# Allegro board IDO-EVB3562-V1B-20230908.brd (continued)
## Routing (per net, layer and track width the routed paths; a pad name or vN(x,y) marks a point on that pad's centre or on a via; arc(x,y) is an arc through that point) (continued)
GND_EARTH: length 94.1
  TOP w0.508: 55.18,78.75 55.18,79.33 ; 31.91,78.52 31.91,79.31 ; 51.31,79.33 51.31,78.87
  TOP w1.016: 54.64,79.28 55.18,78.75 J21.SH1 J22.SH2 51.31,78.87 51.72,79.28 ; 32.8,79.41 31.91,78.52 J23.13 J22.SH1 35.62,78.24 34.45,79.41 ; 15.4,79.28 16.42,78.26 J23.14 15.78,77.88 15.27,78.39 ; J21.SH2 70.87,78.36 71.79,79.28
  L2-VCC w0.508: 35.62,78.24 35.62,79.33
  L2-VCC w1.016: 51.98,79.28 51.31,78.62 J22.SH2 J21.SH1 55.18,78.11 54.01,79.28 ; J23.14 16.42,78.39 15.53,79.28 ; 32.67,79.28 31.91,78.52 J23.13 J22.SH1 35.62,78.24 34.45,79.41 ; 71.41,79.41 70.87,78.87 J21.SH2 71.02,77.88 71.91,78.77
  L3-GND w0.508: 70.87,78.36 70.87,79.33 ; 16.42,79.31 16.42,78.26
  L3-GND w1.016: 52.1,79.41 51.31,78.62 J22.SH2 J21.SH1 55.18,78.36 54.01,79.53 ; 15.4,79.28 16.42,78.26 J23.14 15.78,77.88 15.27,78.39 ; J21.SH2 70.87,78.36 71.79,79.28 ; 34.2,79.28 35.6,77.88 J22.SH1 J23.13 31.91,78.39 32.8,79.28
  BOTTOM w0.508: 31.91,78.52 31.91,79.31 ; 35.47,77.88 34.17,77.88 ; 51.31,78.62 51.31,79.33
  BOTTOM w1.016: 71.15,79.41 70.87,79.13 J21.SH2 ; 16.16,77.88 J23.14 16.42,78.52 15.65,79.28 ; 16.16,77.88 14.76,77.88 14.51,77.63 ; 16.16,77.88 15.02,79.03 ; 34.32,79.03 35.47,77.88 J22.SH1 J23.13 31.91,78.52 32.67,79.28 ; J21.SH2 71.28,77.88 72,78.6 72,78.64 71.83,78.8 71.79,78.8 J21.SH2 ; J22.SH2 51.31,78.62 52.03,79.34 53.72,79.34 J21.SH1 J22.SH2
  vias: v1(15.09,89.22) v1(15.27,86.65) v1(15.27,83.98) v1(15.27,81.19) v1(17.08,89.22) v1(18.07,88.04) v1(18.35,89.22) v1(19.62,89.22) v1(20.89,89.22) v1(20.86,88.04) v1(22.16,89.22) v1(23.43,89.22) v1(23.53,88.04) v1(24.7,89.22) v1(25.97,89.22) v1(27.34,89.22) v1(27.59,88.04) v1(28.61,89.22) v1(29.88,89.22) v1(31.15,89.22) v1(31.66,88.04) v1(32.42,89.22) v1(33.69,89.22) v1(33.69,86.39) v1(33.69,83.6) v1(33.69,80.93) v1(33.69,76.99) v1(34.96,89.22) v1(35.72,88.04) v1(36.23,89.22) v1(37.5,89.22) v1(38.77,89.22) v1(39.66,88.04) v1(40.04,89.22) v1(41.31,89.22) v1(42.78,89.21) v1(43.85,88.04) v1(44.05,89.21) v1(45.32,89.21) v1(46.59,89.21) v1(47.78,88.04) v1(47.86,89.21) v1(49.13,89.21) v1(50.4,89.21) v1(51.67,89.21) v1(51.85,88.04) v1(52.94,89.21) v1(53.12,85.5) v1(53.12,82.71) v1(53.25,79.41) v1(53.25,76.99) v1(54.21,89.21) v1(55.48,89.21) v1(55.91,88.04) v1(56.75,89.21) v1(58.15,89.21) v1(59.42,89.21) v1(59.98,88.04) v1(60.69,89.21) v1(61.96,89.21) v1(63.23,89.21) v1(64.04,88.04) v1(64.5,89.21) v1(65.77,89.21) v1(66.71,88.04) v1(67.04,89.21) v1(68.31,89.21) v1(69.58,89.21) v1(70.85,89.21) v1(70.77,88.04) v1(71.91,85.5) v1(71.91,82.84) v1(71.91,80.17) v1(72.12,89.21)
VCC1V2_DVP: length 66.4
  TOP w0.203: 5.88,19.08 5.81,19.01 J20.22
  TOP w0.254: C1023.2 36.71,7.56 J18.28
  TOP w0.508: C1030.2 7.77,20.1 v1(7.31,19.65) 6.75,19.08 5.88,19.08 ; v1(30.72,7.91) 30.72,3.35 31.66,2.41 36.3,2.41 37.07,3.18 v1(37.07,4.34) ; R136.2 C1048.2 50.64,8.26 v1(50.32,7.95) 55.76,7.95 C104.2 56.22,9.55 C103.2 56.2,9.58 55.56,9.58 55.2,9.22 U13.5 ; C1023.2 v1(38.01,8.16)
  BOTTOM w0.508: v1(50.32,7.95) 50.32,5.64 49.03,4.34 v1(37.07,4.34) ; 19.86,9.3 25.69,9.3 27.08,7.91 v1(30.72,7.91) 32.09,9.28 34.27,9.28 35.52,8.03 37.88,8.03 v1(38.01,8.16)
VCC1V5_DVP: length 19.3
  TOP w0.254: R138.2 C369.2 15.2,10.77 16.67,9.3 16.67,8.97 17.61,8.03 18.88,8.03 19.15,8.31 C108.2
  TOP w0.305: J19.3 23.71,7.37 24.67,8.34 24.67,8.6 C1026.2
  TOP w0.508: v1(25.3,8.43) 25.18,8.55 C1026.2 ; v1(19.84,8.54) 19.72,8.67 C108.2 19.15,9.81 C107.2 19.27,9.94 U14.5
  BOTTOM w0.508: v1(25.3,8.43) 25.19,8.54 v1(19.84,8.54)
VCC1V8_DVP: length 63.3
  TOP w0.203: J20.24 5.52,19.41 6.33,20.22 6.33,20.65 6.8,21.11 7.79,21.11
  TOP w0.254: C101.2 31.34,16.41 31.2,16.27 27.79,16.27 27.27,16.79 R134.2 ; J18.27 37.21,7.36 37.47,7.63 38.22,7.63 38.54,7.95 38.54,8.37 C1027.2
  TOP w0.305: C1024.2 24.16,8.44 23.21,7.48 J19.4 ; v1(9.48,17.1) 9.49,17.1 10.88,17.1 11.15,17.37 R417.2
  TOP w0.508: 32.04,16.03 30.64,14.64 30.64,9.3 30.06,8.72 v1(30.06,7.25) ; C1029.2 7.79,21.11 v1(7.15,20.48) ; v1(22.49,7.72) 22.59,7.72 23.98,9.11 C1024.2 ; C1027.2 v1(39.02,8.21) ; R113.2 v1(42.07,8.18)
  BOTTOM w0.508: 13.52,10.5 16.3,7.72 v1(22.49,7.72) 24.19,7.72 24.65,7.25 v1(30.06,7.25) 32.42,7.25 32.52,7.35 38.16,7.35 v1(39.02,8.21) 39.02,7.91 39.53,7.4 41.29,7.4 v1(42.07,8.18)
VCC2V8_DVP: length 27.5
  TOP w0.203: J20.8 4.85,16.19 5.09,16.19 5.22,16.06 5.85,16.06 6.81,17.03 C1028.2 ; 3.43,19.81 J20.25
  TOP w0.254: C98.2 11.91,9.42 11.54,9.05 10.14,9.05 9.88,9.31 R132.2
  TOP w0.381: v1(5.57,21.22) 4.22,21.22 3.82,20.81 3.82,20.2 3.43,19.81
  TOP w0.508: C1028.2 7.84,16.72 7.22,16.1 v1(6.88,16.1)
  BOTTOM w0.508: v1(11.92,8.62) 8.77,11.76 8.77,14.18 6.88,16.07 v1(6.88,16.1) 6.88,17.45 4.91,19.42 4.91,20.8 5.33,21.22 v1(5.57,21.22)
VCC2V8_DVP1: length 5.7
  TOP w0.254: C1016.2 28.17,9.93 27.9,9.66 26.83,9.66 26.7,9.79 26.7,10.5 26.11,11.09 24.71,11.09 24.09,11.71 R1066.2
VCC2V8_DVP2: length 12.4
  TOP w0.254: J18.24 38.71,7.47 38.89,7.65 39.28,7.65 v1(39.78,8.16) ; C1020.2 35.28,8.59 34.96,8.26 34.04,8.26 33.67,7.89 31.8,7.89 31.59,8.1 C1025.2 R1069.2
  BOTTOM w0.508: v1(39.78,8.16) 39.78,8.54 39.28,9.05 37.85,9.05 37.56,8.76 v1(35.96,8.76)
VCC3V3_E: length 19.1
  TOP w0.381: C1041.2 98.14,27.34 97.57,27.34 97.06,26.83 97.06,22.38 98.71,20.73 102.65,20.73 103.28,21.37 104.63,21.37 106.15,22.89 C1039.2 R1170.2
VCC3V3_PHY0: length 54
  TOP w0.508: v1(45.56,49.73) 45.67,49.84 49.55,49.84 v1(50.18,49.21) ; v1(58.11,64.37) 55.48,64.37 53.63,66.23 R189.2 R175.2 52.61,67.02 51.94,66.35 51.75,66.35 49.53,64.13 v1(49.53,63.94)
  BOTTOM w0.203: U16.40 51.93,59.11 51.72,59.32 51.72,59.7 ; 52.66,54.03 52.99,54.36 U16.29
  BOTTOM w0.381: 51.72,59.7 51.17,60.25 51.17,61.31 50.14,62.34 50.14,62.51 C334.2
  BOTTOM w0.508: v1(50.18,49.21) 50.77,49.8 C360.2 50.9,50.07 51.87,51.04 51.87,52.36 51.68,52.55 C333.2 51.21,53.06 51.86,53.7 52.33,53.7 52.66,54.03 ; C334.2 49.49,63.17 49.49,63.9 v1(49.53,63.94) 47.93,63.94 46.9,62.9 46.9,61.22 46.5,60.82 45.62,60.82 44.27,59.47 44.27,51 45.54,49.73 v1(45.56,49.73) ; v1(58.11,64.37) 58.38,64.37 58.6,64.15 58.6,62.16 58.56,62.11 58.56,60.9 58.92,60.54 C335.2
VCC3V3_PHY2: length 72.2
  TOP w0.508: v1(73.66,73.76) 73.64,73.74 R150.2 73.92,73.06 74.31,72.67 74.31,71.42 73.27,70.38 70.05,70.38 v1(68.18,68.51) ; v1(70.2,61.06) 70.2,57.75 72.17,55.78 v1(72.17,54.77) 72.17,54.47 73.11,53.53 73.11,51.93 73.54,51.49 74.09,51.49 v1(74.75,52.15) ; R157.2 55.4,66.61 56.07,65.94 56.77,65.94 57.66,66.83 57.66,68.68 58.9,69.91 63.78,69.91 65.87,67.82 v1(65.87,66.89)
  BOTTOM w0.203: U15.23 72.69,54.47 C326.2 ; U15.11 76.68,59.05
  BOTTOM w0.254: 71.69,60.25 U15.32
  BOTTOM w0.508: 71.69,60.25 71.48,60.46 70.8,60.46 v1(70.2,61.06) 69.5,61.75 C327.2 69.19,62.09 67.72,63.56 67.72,65.95 66.79,66.89 v1(65.87,66.89) 66.89,67.9 67.57,67.9 v1(68.18,68.51) ; C326.2 v1(72.17,54.77) ; R160.2 78.88,62.59 78.88,66.94 78.74,67.09 78.74,68.62 73.66,73.7 v1(73.66,73.76) ; v1(74.75,52.15) 74.96,52.37 R161.1 R156.1
VCC3V3_SD_OUT: length 28.8
  TOP w0.508: v1(88.42,31.91) 86.65,31.91 84.41,29.67 84.41,28.53 83.07,27.19 M1.9
  TOP w1.016: v1(102.89,32.03) 102.13,32.03 v1(102.09,31.99) 101.97,31.99 101.1,32.86 93.22,32.86 92.79,32.44 91.47,32.44 ; v1(101.87,55.88) 101.87,51.11 v1(103.54,49.44) v1(103.54,48.65)
  vias: v1(90.08,33.94) v1(90.58,33.31) v1(101.19,55.89) v1(109.63,69.76) v1(110.27,69.76)
VCC3V3_SY8368: length 2.4
  TOP w0.254: C814.1 22.41,57.31 23.51,56.21 U70.8
VCC3V3_SYS: length 181.3
  TOP w0.254: v1(68.2,37.55) 68.2,39.63 68.68,40.1 68.68,42.51 67.98,43.21 67.98,48.28 64.57,51.68 64.57,52.84 61.63,55.79 v1(61.63,57.82) ; v1(75.74,73.32) 75.74,70.91 73.82,68.99 70.52,68.99 67.34,65.82 67.34,64.93 66.2,63.79 v1(65.06,63.79) ; v1(23.4,32.16) C31.2 R8.2 ; R431.1 111.3,72.75 111.03,72.47 v1(111.03,70.9) ; v1(92.11,74.58) 94.01,72.68 94.01,71.28 v1(92.87,70.14) ; v1(107.98,64.17) 107.35,63.53 v1(97.31,63.53)
  TOP w0.381: 59.77,25.61 59.77,19.87 60.3,19.34 60.98,19.34 v1(61.46,18.86) ; v1(63.91,16.31) 66.23,14 67.6,14 68.36,13.24 D48.A ; v1(17.79,32.32) 17.79,29.47 17.15,28.83 4.89,28.83 3.46,30.26 2.19,30.26 1.72,30.73 1.72,42 2.5,42.78 v1(5.37,42.78)
  TOP w0.508: R241.1 128.27,24.62 128.5,24.39 R1174.2 ; 122.11,33.08 121.44,32.42 R1211.1
  TOP w0.762: v1(120.07,34.42) v1(120.76,34.42) 122.38,32.8 125.38,32.8 125.59,32.6 129.98,32.6 130.59,31.99 130.59,26.07 129.19,24.67 R241.1
  BOTTOM w0.254: v1(92.11,74.58) 91.85,74.33 81.31,74.33 79.79,72.8 76.26,72.8 v1(75.74,73.32) ; v1(61.63,57.82) 62.16,57.82 65.06,60.71 v1(65.06,63.79) ; v1(111.03,70.9) 111.03,67.22 v1(107.98,64.17) ; v1(97.31,63.53) 96.17,63.53 92.49,67.22 92.49,69.76 v1(92.87,70.14)
  BOTTOM w0.381: v1(61.46,18.86) 63.91,16.41 v1(63.91,16.31) ; R62.1 6.64,44.15 5.37,42.88 v1(5.37,42.78)
  vias: v1(16.67,33.56) v1(28.99,31.15) v1(28.99,30.39) v1(31.27,39.1) v1(32.04,39.1) v1(32.04,38.34) v1(32.04,37.7) v1(43.92,32.88) v1(43.92,32.11) v1(43.92,31.35) v1(44.69,32.88) v1(44.69,32.11) v1(44.69,31.35) v1(61.83,35.9) v1(61.83,35.14) v1(62.59,35.9) v1(62.59,35.14) v1(92.11,35.97) v1(92.11,35.21) v1(92.87,35.97) v1(92.87,35.21) v1(107.7,33.59) v1(109.1,33.64)
VCC5V0_HUB2: length 1.1
  TOP w1.016: 91.47,77.5 91.07,77.1 J42.10
VCC5V0_HUB3: length 2.3
  TOP w0.508: J7.1 132.11,62.2 ; J7.1 132.11,60.64 ; J7.1 131.34,61.42
VCC5V0_HUB4: length 2.3
  TOP w0.508: 132.11,49.21 J8.1 ; J8.1 131.34,49.99 ; J8.1 132.11,50.77
VCC5V_SYS: length 13.9
  TOP w0.127: v1(88.63,24.98) 88.87,25.21 89.57,25.21
  TOP w0.254: 21.75,44.08 21.75,45.88 20.23,47.4 20.23,51.09 19.52,51.79 C815.1 19.52,54.71 19.46,54.77 R787.1
  TOP w0.381: R1168.2 v1(107.68,69.76)
  vias: v1(24.15,37.75) v1(24.16,38.39) v1(24.8,38.39) v1(24.8,37.75) v1(25.43,38.39) v1(25.43,37.75) v1(75.72,32.04) v1(75.72,31.27) v1(76.49,32.04) v1(76.49,31.27) v1(79.1,42.96) v1(79.1,42.27) v1(79.79,42.96) v1(79.79,42.27) v1(80.47,42.96) v1(80.47,42.27) v1(87.28,56.67) v1(87.28,55.91) v1(88.04,56.67) v1(88.04,55.91) v1(88.22,25.38) v1(88.53,25.94) v1(89.11,25.99) v1(89.67,25.99) v1(97.57,71.28) v1(98.33,71.28) v1(99.09,71.79) v1(99.47,22.22) v1(99.47,21.5) v1(100.21,22.22) v1(100.24,21.5) v1(101,22.22) v1(101,21.5) v1(104.43,73.44) v1(105.32,73.31) v1(106.2,73.44) v1(123.73,35.59) v1(123.73,34.96) v1(124.37,35.59) v1(124.37,34.96) v1(125,35.59) v1(125,34.96) v1(126.65,47.4) v1(126.65,46.77) v1(127.03,56.93) v1(127.29,47.4) v1(127.29,46.77) v1(127.67,57.06) v1(127.92,57.56)
VCC_1V8_OUT: length 158.1
  TOP w0.381: R16.1 21.88,12.68 22.18,12.98 22.18,15.56 21.88,15.86 v1(21.88,16.42) ; v1(19.9,28.99) 21.08,30.18 21.08,33.2 19.99,34.3 ; v1(21.14,39.98) 21.14,38.98 21.64,38.48 21.64,35.95 19.99,34.3 ; R1197.2 10.25,34.68 11.51,35.93 14.23,35.93 14.83,35.34 16.61,35.34 17.65,34.3 19.99,34.3 ; v1(37.27,17.13) 37.27,15.44 38.26,14.45 R14.1 R13.1 ; R15.1 22.94,12.09 22.94,15.99 v1(22.89,16.04) ; v1(30.45,28.33) 30.45,27.27 31.15,26.58 31.15,25.94 31.47,25.62 R1078.1 31.78,25.18 31.71,25.11 R382.1
  TOP w0.508: v1(85.88,37.12) 83.95,35.19 M1.17
  TOP w1.016: v1(34.7,40.69) 34.7,41.82 35.16,42.27 v1(35.16,46.28)
  BOTTOM w0.381: v1(19.9,28.99) 23.22,28.99 24.42,27.8 29.66,27.8 30.18,28.33 v1(30.45,28.33) 30.45,28.59 31.94,30.09 34.24,30.09 34.74,29.59 36.39,29.59 37.88,28.1 37.88,26.18 42.8,21.26 42.8,19.65 40.37,17.22 38.07,17.22 37.98,17.13 v1(37.27,17.13) 35.86,17.13 35.77,17.22 27.42,17.22 27.3,17.09 25.98,17.09 25.31,16.42 23.98,16.42 23.54,15.99 22.94,15.99 v1(22.89,16.04) 22.25,16.04 v1(21.88,16.42)
  BOTTOM w1.016: 15.02,61.5 16.29,60.23 16.29,56.17 15.73,55.61 15.73,49.75 16.19,49.29 16.19,44.92 v1(21.14,39.98) 26.42,39.98 27.12,40.69 v1(34.03,40.69) v1(34.7,40.69) ; v1(35.16,46.28) v1(35.97,46.28) 36.85,46.28 37.77,45.36 40.68,45.36 42.73,43.31 44,43.31 v1(45.56,41.75)
  vias: v1(7.74,63.47) v1(8.42,63.46) v1(46.25,41.07) v1(62.11,38.01) v1(62.14,37.32)
VCC_3V3: length 348.9
  TOP w0.254: v1(128.3,12.35) 128.3,10.62 126.86,9.18 124.26,9.18 v1(124.24,9.15)
  TOP w0.381: v1(106.84,6.85) 106.88,6.89 R425.1 ; C1036.2 110.6,16.03 110.19,15.62 U42.16 ; v1(130.21,43.72) 130.33,43.72 131.35,42.7 131.35,40.55 128.3,37.5 v1(128.3,37.12) ; R415.1 v1(76.74,86.52) ; R19.1 v1(77.76,83.85)
  TOP w0.508: v1(124.19,42.74) 124.21,42.72 124.46,42.72 125.49,41.69 R261.2 ; v1(77.04,73.69) 77.43,73.31 77.43,71.69 v1(77.15,71.41) ; R1077.1 v1(124.24,9.15) ; v1(126.4,81.44) 126.4,77.63 125.1,76.33 125.1,73.69 126.65,72.14 v1(126.65,71.91) 126.3,71.56 125.25,71.56 124.52,72.3 R314.2 ; C1036.2 111.09,16.47 111.69,17.08 111.69,17.71 111.18,18.22 109.51,18.22 109.41,18.32 ; v1(131.35,68.74) 117.06,68.74 R466.1
  TOP w0.762: v1(124.19,42.74) v1(124.19,42.07) 124.19,38.87 125.94,37.12 v1(128.3,37.12) v1(128.3,36.35) ; 105.21,7.65 105.21,8.28 107.95,11.02 107.95,16.34 109.41,17.8 v1(109.41,20.46) ; R437.2 105.04,40.52 104.93,40.62 ; v1(106.74,20.46) 106.74,20.68 106.42,21.01 R1201.2 105.39,21.01 104.93,20.56 103.87,20.56 102.78,19.46 101.29,19.46 R299.1 ; 104.93,40.62 v1(104.93,40.67) ; 104.93,40.62 v1(104.93,40.11) ; 104.93,40.62 104.83,40.52 R48.2
  L2-VCC w0.508: J15.5 6.76,36.52 ; J15.5 6.09,35.85 ; J15.5 7.44,35.85
  L2-VCC w0.762: v1(38.58,65.79) 42.76,65.79 43.11,65.44 v1(58.15,65.44) 57.61,65.98 57.61,68.21 59.24,69.83 63.79,69.83 65.92,67.7 68.99,67.7 71.91,70.62 76.75,70.62 77.15,71.02 v1(77.15,71.41)
  BOTTOM w0.254: R460.2 128.87,12.35 v1(128.3,12.35)
  BOTTOM w0.381: v1(126.65,71.91) 129.83,68.74 v1(131.35,68.74) 132.65,68.74 133.27,68.11 133.27,48.62 131.86,47.21 131.86,45.5 130.21,43.85 v1(130.21,43.72)
  BOTTOM w0.508: v1(77.04,73.69) 77.04,83.14 v1(77.76,83.85) 77.76,85.5 v1(76.74,86.52) ; J15.5 7.59,35.85 ; J15.5 6.76,36.67 ; J15.5 6.76,35.02 ; v1(58.15,65.44) 58.43,65.44 v1(58.61,65.26) ; R465.1 v1(126.4,81.44)
  BOTTOM w0.762: 29.37,69.1 29.37,68.23 27.34,66.2 v1(8.69,66.2) ; 29.37,69.1 v1(28.43,69.1) ; 29.37,69.1 29.37,69.3 28.56,69.3 ; v1(27.87,69.07) 28.15,69.07 28.18,69.1 v1(28.43,69.1) ; L12.1 v1(38.58,65.31) v1(38.58,65.79) ; 28.56,69.3 28.23,69.3 v1(27.87,69.65) ; 28.56,69.3 28.43,69.17 v1(28.43,69.1) ; v1(128.3,37.12) v1(128.3,36.35) 128.05,36.1 128.05,24.16 126.78,22.89 123.35,22.89 121.32,20.86 121.32,16.92 123.48,14.76 123.48,11.24 123.35,11.12 123.35,10.32 124.24,9.43 v1(124.24,9.15) 122.8,7.72 118.36,7.72 117.49,6.85 v1(106.84,6.85) v1(104.55,6.85) v1(103.79,6.85) 98.9,6.85 98.07,6.02 86.03,6.02 84.26,4.26 73.49,4.26 ; v1(72.48,4.26) v1(73.07,4.26) 73.49,4.26 ; R194.1 61.75,63.13 60.31,64.57 59.42,64.57 58.66,65.34 58.61,65.34 v1(58.61,65.26) ; 73.49,4.26 73.49,4.58 v1(73.54,4.63) ; v1(77.15,71.41) v1(77.52,71.04) 79.5,69.06 79.5,67.4 79.64,67.26 79.64,63.1 79.99,62.76 R160.1 ; v1(124.19,42.74) v1(124.19,42.07) 123.15,41.03 123.15,40.88 119.58,37.31 107.51,37.31 104.93,39.89 v1(104.93,40.11) v1(104.93,40.67) ; v1(106.74,20.46) v1(109.41,20.46)
  vias: v1(6.38,38.51) v1(7.14,38.51) v1(7.6,64.29) v1(7.91,38.51) v1(8.27,64.29) v1(8.67,65.52) v1(8.67,64.84) v1(13.47,15.68) v1(13.98,16.31) v1(19.9,14.94) v1(20.38,15.93) v1(26.83,26.7) v1(27.59,26.7) v1(28.1,25.94) v1(28.35,26.7) v1(28.48,69.68) v1(28.76,15.02) v1(28.76,14.38) v1(35.54,13.7) v1(36.1,13.27) v1(55.53,12.82) v1(56.29,12.82) v1(73.31,10.7) v1(73.31,10.07) v1(73.95,10.7) v1(73.95,10.07)
VCC_3V3_OUT: length 180
  TOP w0.254: v1(73.82,11.84) 73.69,11.84 72.55,10.7 R11.1 ; R12.1 73.38,13.62 v1(73.69,13.62)
  TOP w0.381: v1(97.57,7.48) 97.8,7.48 99.5,9.18 105.13,9.18 107.26,11.31 107.26,16.63 108.62,18 108.62,23.07 110.21,24.66 R391.2
  TOP w0.508: R383.1 v1(47.59,68.17) ; M1.7 81.32,25.19 81,24.86 81,20.67 79.98,19.65 v1(77.74,19.65) ; v1(83.5,51.59) 84.95,50.14 R384.1 ; v1(65.84,19) 65.84,20.18 64.85,21.17 64.85,22.56 65.88,23.59 65.88,26.14 67.32,27.58 67.32,29.77 66.78,30.31 66.78,40.55 66.35,40.98 66.35,42.18 v1(65.59,42.93) 65.59,46.37 63.89,48.07 63.89,49.31 62.9,50.31 62.9,52.27 56.23,58.94 52.12,58.94 51.74,59.32 49.55,59.32 48.4,60.47 46.65,60.47 46.23,60.9 v1(46.23,61.48) ; v1(77.38,16.67) 77.38,15.65 77.61,15.42 77.61,14.24 76.99,13.62 v1(73.69,13.62)
  BOTTOM w0.254: v1(73.82,11.84) 73.82,13.49 v1(73.69,13.62)
  BOTTOM w0.381: v1(97.57,7.48) 97.57,7.61 96.96,8.21 95.76,8.21 95.57,8.41 94.58,8.41 94.09,7.92 86.72,7.92 81.95,12.68 81.95,14.48 79.76,16.67 v1(77.38,16.67)
  BOTTOM w0.508: v1(83.5,51.59) 81.82,49.92 81.82,47.51 78.82,44.5 67.16,44.5 v1(65.59,42.93) ; v1(65.84,19) 68.61,16.23 71.09,16.23 v1(73.69,13.62) ; v1(46.23,61.48) 45.97,61.73 45.97,66.56 v1(47.59,68.17) ; v1(77.74,19.65) 77.38,19.29 v1(77.38,16.67)
VCC_DCIN: length 35.9
  TOP w0.508: 11.73,75.01 F3.1 13.48,75.01
  TOP w1.524: J1.4 3.11,83.35 3.79,84.03 7.68,84.03 9.02,82.68 9.02,79.61 12.61,76.03 F3.1
  L2-VCC w0.508: 2.7,28.51 J43.5 ; J43.5 1.92,29.29 ; J43.5 3.48,29.29 ; J43.5 2.7,30.07 ; F3.1 13.48,75.01 ; F3.1 11.73,75.01 ; F3.1 12.61,75.89 ; F3.1 12.61,74.14 ; J43.6 3.48,27.29 ; J43.6 2.7,28.07 ; J43.6 1.92,27.29 ; J15.1 7.44,27.85 ; J15.1 6.76,28.52 ; J15.1 6.09,27.85 ; J1.4 4.09,81.4 ; J1.4 3.11,83.08 ; J1.4 2.13,81.4 ; J1.4 3.11,79.72
  vias: v1(10.45,75.47) v1(10.45,74.71) v1(10.55,76.18) v1(11.21,76.23) v1(11.97,76.23) v1(12.73,76.23)
VCC_LEDA+: length 15.4
  BOTTOM w0.508: U10.5 6.26,51.8 6.59,52.13 8.34,52.13 8.97,52.76 8.97,58.22 8.34,58.86 4.47,58.86 4.26,59.06 D18.C
  vias: v1(4.63,58.96) v1(4.86,66.86) v1(4.99,60.99) v1(4.99,60.23) v1(4.96,59.55) v1(5.19,66.35)
VCC_LEDK-: length 10.6
  TOP w0.254: v1(5.49,57.08) 5.57,57.16 5.57,62.77 5.09,63.25 5.09,65.04 v1(5.37,65.31)
  BOTTOM w0.254: R84.2 6.94,56.44 6.13,56.44 v1(5.49,57.08)
  vias: v1(4.81,65.31)
VCC_M2:
  vias: v1(95.55,31.59) v1(95.54,30.91) v1(95.55,30.23) v1(95.55,29.55) v1(95.55,28.88) v1(95.55,28.2) v1(95.65,45.75) v1(96.31,45.61) v1(96.3,44.99) v1(96.54,38.44) v1(96.54,37.76) v1(96.93,45.63) v1(97,44.95) v1(97.31,38.44) v1(97.31,37.76) v1(98.07,38.44) v1(98.07,37.76)
VCC_OUT: length 37.4
  TOP w0.508: J44.1 122.84,5.51 ; J44.1 123.87,4.48 ; J44.1 121.81,4.48 ; J44.1 122.84,3.45
  BOTTOM w0.508: 122.84,3.45 J44.1 ; J44.1 121.81,4.48 ; J44.1 123.87,4.48 ; J56.1 132.17,24.87 133.38,23.65 133.38,11.08 132.49,10.19 128.18,10.19 v1(124.37,6.38) ; J55.1 90.25,3.67 ; J55.1 89.47,2.9 ; J55.1 91.03,2.9 ; J55.1 90.25,2.12
  vias: v1(87.87,4.5) v1(88.63,4.5) v1(89.39,4.5) v1(123.73,5.75) v1(124.37,5.75)
VCC_RMII: length 56.1
  TOP w0.254: v1(35.21,49.27) 34.36,49.27 33.31,50.32 33.31,52.16 R1200.2
  TOP w0.381: R219.1 v1(34.9,70.9)
  TOP w0.508: v1(41.69,57.18) 41.18,57.18 40.77,57.59 40.18,57.59 39.92,57.84 39.92,59.85 40.24,60.17 v1(40.41,60.17) 40.16,60.42 v1(40.16,61.16) ; v1(39.94,64.26) 38.32,64.26 36.36,62.29 36.36,60.75 36.16,60.56 36.16,52.04 v1(35.21,51.09) v1(35.21,49.27)
  BOTTOM w0.254: 37.37,56.42 37.23,56.56 U17.14
  BOTTOM w0.381: v1(34.9,70.9) 35.39,70.9 41.37,64.92 C159.2 ; v1(40.41,60.17) 39.84,59.6 R212.2
  BOTTOM w0.508: v1(35.21,49.27) 33.58,49.27 32.54,50.3 R207.1 R205.1 ; 37.37,56.42 C338.2 38.7,56.09 39.06,55.74 40.88,55.74 41.69,56.55 v1(41.69,57.18) 41.16,57.72 40.52,57.72 39.78,58.45 R195.2 ; R204.2 v1(35.21,51.09)
VCC_SIM: length 14.1
  TOP w0.508: R52.2 R53.2 v1(119.74,53.02) ; 114.33,59.6 114.33,56.57 114.71,56.19 v1(114.71,55.52) R440.2
  BOTTOM w0.508: v1(119.74,53.02) 119.74,52.98 119.14,52.39 118.58,52.39 117.85,53.12 115.98,53.12 114.71,54.39 v1(114.71,55.52)
  vias: v1(109.53,60) v1(110.29,60) v1(116.31,59.06) v1(117.1,59.06)
VCC_SYS: length 7
  TOP w0.305: v1(22.99,53.37) 22.82,53.2 21.77,53.2 21.43,53.54 R783.1
  BOTTOM w0.305: v1(24.42,57.76) 24.42,56.8 22.99,55.38 v1(22.99,53.37)
VCC_TP: length 5.9
  TOP w0.254: R449.2 R422.2 R421.2 10.25,32.56 11.15,33.46 C285.2
  TOP w0.508: R423.2 14.78,34.58 14.02,35.34 12.78,35.34
VCCA_RMII: length 18.2
  TOP w0.508: v1(30.77,57.69) 30.77,54.37 31.51,53.63 32.05,53.63 32.56,54.14 32.56,57.09 35.51,60.04 v1(35.51,61.25)
  BOTTOM w0.254: C336.2 29.69,58.71 30.67,58.71 31.31,58.06 U17.30
  BOTTOM w0.508: v1(30.77,57.69) 30.26,58.2 29.69,58.2 C336.2
VCCIO4_IN: length 6.2
  TOP w0.508: R384.2 C271.2 86.32,48.11 85.25,49.19 M1.31
VCCIO5_IN: length 6.4
  TOP w0.508: R383.2 C270.2 49.56,66.83 49.94,66.46 49.94,65.43 48.87,64.37 M1.76
VCCIO6_IN: length 12.7
  TOP w0.381: 37.57,32.19 35.71,32.19 33.61,30.08 33.61,24.33 33.05,23.78 C269.2 R382.2
VCCIO_PHY0: length 50.3
  TOP w0.381: v1(54.49,50.07) 50.42,50.07 50.08,50.41 44.62,50.41 v1(43.49,49.28)
  TOP w0.508: v1(54.49,50.07) 54.49,50.07 v1(57.13,50.07) 57.25,50.07 v1(58.06,49.26) 58.56,48.75 58.85,48.75 v1(59.31,48.29) 59.77,47.83 59.77,46.06 v1(60.7,45.13)
  BOTTOM w0.203: 53.39,54.08 U16.28
  BOTTOM w0.381: v1(60.7,45.13) 63.85,48.28 63.85,53.94 62.67,55.12 62.67,55.51 60.74,57.44 R191.2 ; v1(43.49,49.28) 43.2,49.56 43.16,49.56 R188.2 ; v1(59.31,48.29) 60.1,49.09 R178.2 ; v1(58.06,49.26) 58.06,49.62 R185.2
  BOTTOM w0.508: R182.2 57.82,50.88 57.13,50.19 v1(57.13,50.07) ; v1(54.49,50.07) C358.2 53.35,50.41 53.35,52.25 53.05,52.55 C361.2 52.61,53.02 53.39,53.8 53.39,54.08
VDD10_PHY0: length 45.9
  TOP w0.508: v1(59.81,54.43) 58.05,56.19 52.69,56.19 51.98,56.9 51.98,57.65 v1(50.96,58.66) ; v1(55.39,60.36) 53.52,60.36 v1(53.39,60.48) 53,60.88 v1(50.18,60.88) ; v1(47.28,51.72) v1(44.99,51.72)
  BOTTOM w0.203: U16.3 v1(53.39,60.48) ; U16.21 56.19,54.72 56.33,54.58 56.87,54.58 ; v1(50.96,58.66) 50.99,58.63 51.28,58.63 51.6,58.31 U16.38 ; U16.8 v1(55.39,60.36)
  BOTTOM w0.508: C328.2 60.75,52.92 60.75,53 59.81,53.94 v1(59.81,54.43) 59.66,54.58 56.87,54.58 ; v1(50.96,58.66) 50.82,58.81 50.82,59.12 50.18,59.75 v1(50.18,60.88) 49.94,61.12 C332.2 49.51,60.68 49.15,60.33 46.9,60.33 46.76,60.18 45.88,60.18 44.9,59.21 44.9,51.81 v1(44.99,51.72) ; v1(55.39,60.36) 55.39,61.05 C331.2 ; C330.2 53.19,60.69 v1(53.39,60.48)
VDD10_RTL: length 32.7
  TOP w0.508: v1(73.82,52.16) 73.82,53.8 73.12,54.51 73.12,55.72 70.86,57.99 v1(70.86,59.34) 70.86,60.44 71.65,61.24 v1(73.09,61.24) 73.1,61.25 v1(75.09,61.25)
  BOTTOM w0.203: U15.3 v1(73.09,61.24) ; U15.8 75.09,60.49 75.85,61.25 75.85,61.71 76.23,62.09 76.23,62.83 C322.2 ; C324.2 69.76,59.15 70.13,59.15 70.52,58.76 71.06,58.76 71.35,59.05 U15.30 ; 73.18,55.54 73.09,55.62 U15.22
  BOTTOM w0.381: v1(75.09,61.25) 75.09,61.61 75.81,62.32 75.81,62.66 C322.2 ; C324.2 70.34,59.72 70.72,59.34 v1(70.86,59.34)
  BOTTOM w0.508: v1(73.09,61.24) 72.17,62.16 72.16,62.16 71.53,62.79 C323.2 ; v1(73.82,52.16) 73.58,51.92 R159.2 73.12,51.98 C126.1 C321.2 73.18,54.07 73.18,55.54
VDD_3V8: length 11.6
  TOP w0.254: v1(94.03,50.54) 94.03,51.42 C80.2 ; R60.2 C79.2 90.46,49.1 v1(90.99,48.57)
  TOP w0.508: R452.2 93.89,59.34 94.01,59.47 95.92,59.47 96.55,58.83
  BOTTOM w0.254: v1(90.99,48.57) 91.78,49.36 92.86,49.36 v1(94.03,50.54)
  vias: v1(96.86,57.26) v1(96.86,56.47) v1(96.86,55.63) v1(97.59,55.66) v1(98.33,55.63) v1(99.09,55.63) v1(102.01,67.72) v1(102.01,67.09) v1(102.83,67.7) v1(102.78,67.09) v1(103.66,67.7) v1(104.53,67.7) v1(105.72,55.79) v1(106.33,55.79) v1(106.97,55.76) v1(107.6,55.76) v1(108.24,55.79) v1(108.77,56.12) v1(120.84,53.04) v1(121.44,53.04)
VDD_5V: length 49.3
  TOP w0.305: v1(83.98,7.14) 84.58,7.14 v1(85.31,6.41)
  TOP w0.508: U43.3 125.64,12.35 125.58,12.41 C532.1 124.06,12.41 123.12,11.46 v1(122.59,11.46) ; R366.1 121.7,8.92 v1(121.19,9.43)
  BOTTOM w0.254: v1(121.19,9.43) 121.19,10.07 v1(122.59,11.46)
  BOTTOM w0.305: v1(121.19,9.43) 120.28,8.52 117.84,8.52 116.94,7.61 98.62,7.61 97.69,6.68 85.58,6.68 v1(85.31,6.41)
  BOTTOM w0.508: 6.76,31.02 J15.3 ; J15.3 6.76,32.67 ; J15.3 5.94,31.85
  vias: v1(14.76,50.83) v1(14.76,50.2) v1(14.76,49.52) v1(15.04,49.03) v1(79.79,14.38) v1(79.79,13.75) v1(80.42,14.38) v1(80.42,13.75)
VDD_LCD: length 5.8
  TOP w0.508: 6.76,33.02 J15.4 ; J15.4 5.94,33.85 ; J15.4 6.76,34.67 ; J15.4 7.59,33.85 ; J15.2 7.59,29.85 ; J15.2 5.94,29.85 ; J15.2 6.76,30.67
VDD_LCD_: length 6.5
  TOP w1.016: J16.1 13.62,45.18 ; J16.1 J16.2 11.62,45.18 ; J16.1 J16.3 ; J16.1 14.45,46.01
VDD_RTC: length 4.2
  TOP w0.381: D49.C D48.C 67.78,12.66 C190.1 67.34,11.72 67.3,11.68 U20.8
4G_DM: length 2.9
  TOP w0.114: J10.36 103.98,56.36 103.73,56.11 103.73,55.16 R49.2
4G_DP: length 3
  TOP w0.114: R50.2 103.48,55.17 103.48,56.09 103.18,56.4 J10.38
4G_LED_WANN#: length 10.7
  TOP w0.127: J10.42 101.58,58.58 100.31,59.85 96.55,59.85 95.79,60.61 LED2.C
4G_POWER_H: length 82.9
  TOP w0.127: v1(44.59,44.14) 44.38,43.93 41.42,43.93 37.68,40.19 37.57,40.19 ; v1(89.91,39.26) 90.22,39.57 90.22,40.22 94,43.99 94,47.12 95.73,48.85 97.21,48.85 98.91,50.55 98.91,50.94 98.55,51.3 95.03,51.3 94.6,50.87 94.6,50.44 93.39,49.24 R441.1
  BOTTOM w0.127: v1(44.59,44.14) 49.49,39.25 61.6,39.25 64.82,42.47 65.78,42.47 66.27,42.96 75.85,42.96 77.78,41.03 84,41.03 86.51,38.51 89.16,38.51 v1(89.91,39.26)
ADC0: length 6.2
  TOP w0.127: R350.2 111.92,5.39 111.64,5.11 111.64,2.98 J44.10
ADC1: length 6.3
  TOP w0.127: J44.12 111.28,3.08 111.28,5.14 110.9,5.52 R349.2
ADC2: length 10.9
  TOP w0.127: R348.2 101.28,5.4 101.28,3.63 101.61,3.3 106.24,3.3 J44.14
ADC3: length 8.4
  TOP w0.127: R347.2 101.02,6.16 101.02,3.53 101.51,3.04 103.96,3.04 J44.16
ADC4: length 9
  TOP w0.127: J44.18 101.45,1.94 100.32,3.07 99.21,3.07 98.69,3.59 98.69,5.42 99.39,6.13 99.97,6.13 R346.2
ADC5: length 6.1
  TOP w0.127: J44.20 98.43,3.49 98.43,5.6 R345.2
AF-PWDN: length 9.1
  TOP w0.127: J20.26 5.51,19.81 6.04,20.34 6.04,20.77 6.85,21.58 9.68,21.58 10.15,21.11 10.15,20.37 R416.2
BATDIV: length 4
  TOP w0.254: M1.176 78.56,34.62 79.11,35.17 v1(79.11,35.51)
  BOTTOM w0.254: TP3.1 79.96,35.51 v1(79.11,35.51)
BT_REG_ON_H: length 1
  TOP w0.127: R235.2 R245.1
BT_REG_ON_H_GPIO0_B0_D: length 65
  TOP w0.127: R235.1 113,16.17 v1(112.79,16.17) ; v1(70.24,28.32) 70.51,28.05 70.51,26.56 70.01,26.07 70.01,24.95 70.14,24.82 70.14,24.56 69.67,24.1 69.67,23.34 69.25,22.92 69.25,21.14 70.06,20.33 71.18,20.33 72.73,18.78 75.32,18.78 75.87,18.23 M1.167
  BOTTOM w0.127: v1(112.79,16.17) 112.6,16.35 110.34,16.35 110.16,16.53 103.47,16.53 102.65,17.35 91.91,17.35 87.2,22.06 86.78,22.06 84.48,24.37 83.72,24.37 79.17,28.91 71.55,28.91 70.95,28.32 v1(70.24,28.32)
CAM_CLK0_OUT_M1: length 5.1
  TOP w0.127: R123.1 33.26,40.49 34.57,39.18 36.11,39.18 36.11,39.19 37.57,39.19
CAM_CLK2_OUT: length 112.7
  TOP w0.127: v1(62.45,21.11) 62.45,22.37 64.17,24.09 64.17,24.54 64.63,25 64.63,26.68 66.05,28.1 66.05,29.22 65.54,29.73 65.54,39.91 65.03,40.42 65.03,41.36 64.24,42.15 64.24,45.8 62.57,47.48 62.57,48.93 61.59,49.91 61.59,50.33 61.59,50.54 61.59,51.15 59.82,52.92 59.4,52.92 57.44,54.88 49.47,54.88 48.77,55.58 46.87,55.58 40.87,61.58 M1.84 ; v1(21.59,15.31) 21.59,13.33 21.37,13.11 21.37,9.62 R1179.1
  BOTTOM w0.127: v1(21.59,15.31) 21.73,15.17 24.39,15.17 24.95,15.73 25.53,15.73 26.26,16.45 34.11,16.45 35.13,15.43 37.31,15.43 38.03,14.71 39.76,14.71 40.3,15.26 41.15,15.26 43.02,17.12 52.84,17.12 53.67,16.3 56.73,16.3 59.89,19.46 60.76,19.46 60.88,19.58 62,19.58 62.09,19.67 62.59,19.67 62.98,20.05 62.98,20.59 v1(62.45,21.11)
CAM_CLK3_OUT: length 89.2
  TOP w0.127: R1180.1 42.32,12.23 40.53,14.02 v1(40.53,14.79) ; v1(62.19,19.16) 62.19,19.3 62.98,20.08 62.98,22.39 64.47,23.88 64.47,24.42 64.9,24.85 64.9,26.55 66.33,27.97 66.33,29.34 65.79,29.88 65.79,40.06 65.34,40.52 65.34,41.56 64.55,42.35 64.55,45.91 62.85,47.61 62.85,49.01 61.84,50.02 61.84,50.23 61.84,50.44 61.84,51.39 60.01,53.21 59.53,53.21 57.58,55.16 49.63,55.16 48.9,55.89 47,55.89 41.87,61.01 M1.83
  BOTTOM w0.127: v1(62.19,19.16) 62.02,19.33 61.06,19.33 60.89,19.16 60.05,19.16 56.9,16.02 53.47,16.02 52.64,16.85 43.15,16.85 41.1,14.79 v1(40.53,14.79)
CAN0_H: length 25.8
  BOTTOM w0.203: L45.2 129.7,16.42 128.56,17.56 126.4,17.56 125.99,17.15 D194.A 124.77,16.8 123.98,16.8 122.97,17.81 122.97,20.23 124.24,21.5 127.67,21.5 130.59,24.42 130.59,27.17 J56.2
CAN0_L: length 28.1
  BOTTOM w0.203: J56.3 130.08,28.66 130.08,24.54 127.41,21.88 123.86,21.88 122.46,20.48 122.46,17.56 123.73,16.29 124.77,16.29 D195.A 125.92,15.93 127.03,17.05 128.18,17.05 128.81,16.42 L46.2
CAN0_RX_M2: length 14.9
  TOP w0.127: U43.4 127.29,11.08 127.41,10.95 127.41,10.68 126.55,9.81 124.62,9.81 124.24,10.19 120.56,10.19 117.89,12.86 R1208.2
CAN0_STB_IO: length 1.8
  TOP w0.127: U43.8 132.24,14.89 v1(132.62,14.51)
  BOTTOM w0.127: v1(132.62,14.51) 132.55,14.44 R459.1
CAN0_TX_M2: length 19.3
  TOP w0.127: R1207.2 115.6,11.97 115.98,12.35 118.02,12.35 120.43,9.94 124.13,9.94 124.51,9.56 126.68,9.56 127.67,10.55 127.67,14.43 127.21,14.89 U43.1
CAN0H: length 4.1
  TOP w0.203: U43.7 129.83,13.62 v1(129.57,13.88)
  BOTTOM w0.203: R462.1 129.99,14.17 L45.1 129.57,14.33 v1(129.57,13.88)
CAN0L: length 5.3
  TOP w0.203: U43.6 131.22,12.35 130.33,13.24 129.45,13.24 v1(128.81,13.88)
  BOTTOM w0.203: R461.1 128.52,14.17 L46.1 v1(128.81,13.88)
CIF1_SCL: length 2.5
  TOP w0.127: J18.21 40.21,7.4 41.05,8.24 R126.2
CIF1_SDA: length 2.6
  TOP w0.127: R127.2 40.42,8.47 40.42,8.01 39.71,7.3 J18.22
CIF2_RST: length 9.7
  TOP w0.127: R372.2 10.28,18.19 10.25,18.17 R417.1 9.57,18.36 8.34,18.36 C288.2 6.89,17.86 5.75,16.73 v1(5.44,16.73) ; v1(4.22,16.33) 3.73,16.33 3.21,15.81 J20.5
  BOTTOM w0.127: v1(4.22,16.33) 4.88,16.33 5.27,16.73 v1(5.44,16.73)
CIF2_RST_L: length 71.6
  TOP w0.127: R372.1 13.23,20.65 v1(17.15,20.65) ; v1(21.89,39.07) 22.02,38.94 22.02,29.1 22.99,28.13 22.99,23.15 24.26,21.87 v1(24.26,18.76) ; v1(35.62,39.78) 35.9,40.06 35.9,45.47 36.61,46.18 36.61,59.6 37.2,60.19 37.57,60.19
  BOTTOM w0.127: v1(17.15,20.65) 19.04,18.76 v1(24.26,18.76) ; v1(21.89,39.07) 26.49,39.07 27.41,39.99 35.41,39.99 v1(35.62,39.78)
CIF2_SCL: length 33.3
  TOP w0.127: v1(4.23,18.82) 4.04,19.01 J20.21 ; v1(13.83,5.04) 15.23,3.63 20.42,3.63 21.71,4.91 J19.7 21.71,7.92 R128.2
  BOTTOM w0.127: v1(4.23,18.82) 4.23,18.6 4.44,18.39 4.44,17.73 4.98,17.19 5.64,17.19 5.91,16.92 5.91,15.7 7.82,13.79 7.82,11.34 13.83,5.34 v1(13.83,5.04)
CIF2_SDA: length 32.8
  TOP w0.127: v1(14.94,5.09) 16.14,3.89 20.32,3.89 21.36,4.93 21.36,5.86 21.21,6.01 J19.8 21.21,8.44 R129.2 ; v1(4.22,19.49) 4.14,19.41 J20.23
  BOTTOM w0.127: v1(4.22,19.49) 4.7,19.01 4.7,17.84 5.09,17.45 5.74,17.45 6.16,17.03 6.16,15.8 8.08,13.89 8.08,11.44 14.43,5.09 v1(14.94,5.09)
CIF_EN: length 69.2
  TOP w0.127: v1(53.94,16.79) 53.7,16.54 R374.1 ; R373.1 26.94,21.19 26.14,21.19 25.86,20.91 25.86,20.3 25.45,19.88 25.45,17 v1(24.28,15.83) 24.09,15.65 R1065.1 ; R375.1 R1181.1 19.1,15.74 19.22,15.74 19.95,16.47 20.61,16.47 v1(20.99,16.85) 20.99,17.23 20.26,17.95 14.72,17.95 11.53,14.77 R130.1 ; v1(34.68,16.62) 33.2,15.15 32.86,15.15 R1172.2 R1068.1
  BOTTOM w0.127: v1(53.94,16.79) 53.3,17.43 42.92,17.43 41,15.51 40.15,15.51 39.72,15.08 38.11,15.08 37.47,15.71 35.59,15.71 v1(34.68,16.62) 34.53,16.77 27.52,16.77 27.46,16.71 26.14,16.71 25.47,16.04 24.49,16.04 v1(24.28,15.83) 23.97,15.53 22.11,15.53 21.41,16.22 21.41,16.42 v1(20.99,16.85)
CIF_PDN: length 59.8
  TOP w0.127: R124.2 43.09,8.48 42.12,7.51 41.4,7.51 41.21,7.33 J18.19 41.21,4.27 38.64,1.71 25.04,1.71 22.21,4.54 ; 22.21,4.54 22,4.34 21.49,4.34 20.53,3.38 14.75,3.38 12.6,5.52 v1(12.6,7.57) ; 22.21,4.54 J19.6 ; R416.1 7.53,19.08 7.06,18.61 6.61,18.61 5.97,17.97 v1(5.44,17.97) 5.29,18.12 5.29,18.4 5.08,18.61 J20.20
  BOTTOM w0.127: v1(5.44,17.97) 5.58,17.97 6.42,17.13 6.42,15.91 8.33,14 8.33,11.55 12.31,7.57 v1(12.6,7.57)
CIF_PDN_L: length 95.1
  TOP w0.127: R124.1 42.44,10.4 42.04,10.4 41.82,10.62 41.82,12.38 40.04,14.15 40.04,15.6 v1(39.27,16.37) ; 37.57,59.19 37.69,59.19 38.72,58.16 38.72,56.87 41.11,54.47 48.29,54.47 48.92,53.84 57.02,53.84 59.82,51.03 59.82,50.24 61.53,48.53 61.53,46.98 63.17,45.34 63.17,41.68 63.97,40.87 63.97,39.95 64.5,39.43 64.5,27.31 64.09,26.91 64.09,25.33 63.61,24.85 63.61,24.34 61.29,22.02 61.29,20.95 61.7,20.54 62.25,20.54 v1(62.51,20.28)
  BOTTOM w0.127: v1(39.27,16.37) 39.48,16.58 40.63,16.58 42.62,18.57 57.06,18.57 59.46,20.97 61.25,20.97 61.68,20.55 62.24,20.55 v1(62.51,20.28)
CIF_PWREN_H: length 104.5
  TOP w0.127: v1(35.37,16.62) 33.41,14.66 33.27,14.66 R1172.1 ; R1082.2 R78.2 40.8,64.32 40.14,63.66 38.36,63.66 36.89,62.19 36.89,61.5 37.2,61.19 38.07,61.19 38.51,60.74 38.51,58.72 38.97,58.27 38.97,56.97 41.21,54.73 48.39,54.73 49.03,54.09 57.12,54.09 60.08,51.14 60.08,50.34 61.78,48.64 61.78,47.09 63.42,45.44 63.42,41.78 64.23,40.98 64.23,40.06 64.75,39.53 64.75,27.19 64.35,26.78 64.35,25.2 63.86,24.72 63.86,24.21 61.77,22.13 v1(61.77,21.12)
  BOTTOM w0.127: v1(35.37,16.62) 35.42,16.67 38.12,16.67 38.29,16.84 40.53,16.84 42.52,18.82 56.96,18.82 59.38,21.24 61.65,21.24 v1(61.77,21.12)
CIF_RST: length 31
  TOP w0.127: R125.2 C94.2 41.31,10.52 R113.1 41.56,9.25 41.56,8.11 40.71,7.26 J18.20 40.71,4.13 38.54,1.96 25.14,1.96 22.71,4.4 J19.5
CIF_RST_L: length 90.5
  TOP w0.127: R125.1 40.04,12.17 40.04,13.79 39.76,14.07 39.76,14.96 v1(38.67,16.05) ; v1(61.84,20.07) 61.63,20.28 61.59,20.28 61.03,20.83 61.03,22.14 63.36,24.47 63.36,25.03 63.84,25.51 63.84,27.03 64.24,27.44 64.24,39.2 63.72,39.72 63.72,40.74 62.92,41.54 62.92,45.23 61.27,46.88 61.27,48.43 59.57,50.13 59.57,50.93 56.96,53.54 44.48,53.54 44.44,53.58 41.64,53.58 38.46,56.76 38.46,58.06 38.33,58.19 37.57,58.19
  BOTTOM w0.127: v1(38.67,16.05) 38.81,15.9 39.46,15.9 39.89,16.33 40.74,16.33 42.73,18.32 57.17,18.32 59.57,20.71 61.15,20.71 61.59,20.28 61.63,20.28 v1(61.84,20.07)
CKXTALIN: length 5
  BOTTOM w0.127: XT4.3 28.54,60.6 C156.1 29.05,59.47 31,59.47 31.41,59.06 U17.32
CKXTALOUT: length 8.4
  BOTTOM w0.127: U17.31 31.4,58.56 30.88,59.09 28.3,59.09 C158.2 27.72,60.29 27.72,62.09 XT4.1
CLKREQB: length 5.2
  BOTTOM w0.102: 76.72,58.65 U15.12
  BOTTOM w0.127: 76.72,58.65 77.34,58.65 77.43,58.56 80.18,58.56 80.25,58.64 R155.2
CSI0_MCLK: length 48.8
  TOP w0.127: J20.14 6.08,17.41 7.03,18.36 7.44,18.36 7.69,18.62 9.35,18.62 11.85,21.12 17.89,21.12 19.49,22.72 19.49,27.03 v1(20.86,28.4) ; v1(32.16,28.55) 32,28.71 32,29.64 32.32,29.96 32.32,30.13 34.7,32.51 34.7,37.5 33.75,38.46 C95.2 33.05,38.46 R123.2
  BOTTOM w0.127: v1(20.86,28.4) 21.07,28.61 23.07,28.61 24.26,27.42 30.45,27.42 31.58,28.55 v1(32.16,28.55)
CSI2_MCLK: length 4.8
  TOP w0.127: R1177.1 R1179.2 20.39,9.54 20.39,8.63 20.71,8.32 J19.9
CSI3_MCLK: length 6.1
  TOP w0.127: R1180.2 R1178.1 43.21,10.45 43.62,10.04 43.62,8.51 43.33,8.21 43.18,8.21 42.21,7.24 J18.17
GMAC0_TXCLK_: length 35.7
  TOP w0.127: v1(58.21,47.32) 57.34,47.32 55.99,48.67 50.84,48.67 50.53,48.36 43.2,48.36 41.85,49.71 v1(41.85,51.72)
  BOTTOM w0.127: v1(41.85,51.72) 41.87,51.7 C132.2 R177.2 ; U16.20 57.56,55.51 57.92,55.15 59.97,55.15 60.51,54.61 60.51,54.23 61.64,53.09 61.64,49.25 59.72,47.32 v1(58.21,47.32)
GMAC1_RSTN: length 4.6
  BOTTOM w0.203: R172.2 R190.1 C364.2 59.02,58.71 U16.12
GMAC1_RSTN_GPIO0_A6_D: length 54.2
  TOP w0.127: v1(61.95,59.41) 62.17,59.41 63.49,58.09 63.49,55.9 66.24,53.15 66.24,52.1 70.43,47.91 70.43,38.94 69.73,38.23 69.73,34.37 69.19,33.83 69.19,32.34 71.01,30.51 71.01,26.31 70.52,25.81 70.52,25.31 70.9,24.93 70.9,24.61 70.18,23.89 70.18,23.13 69.76,22.71 69.76,21.37 70.29,20.84 71.43,20.84 72.98,19.28 75.53,19.28 75.78,19.03 76.49,19.03 76.59,18.93 76.94,18.93 77.22,18.65 77.4,18.65 77.87,18.18 M1.169
  BOTTOM w0.127: R172.1 v1(61.95,59.41)
GPIO0_A5_D: length 58
  TOP w0.127: v1(88.27,59.49) 90.49,59.49 R429.2 R430.2 ; v1(80.37,49.13) 80.96,48.55 80.96,33.36 80.73,33.13 80.73,26.93 79.66,25.86 79.66,24.21 79.28,23.83 76.72,23.83 74.81,21.93 74.81,20.48 75.98,19.31 76.64,19.31 76.77,19.18 77.14,19.18 77.42,18.91 78.41,18.91 78.87,18.45 M1.170
  BOTTOM w0.127: v1(80.37,49.13) 80.58,49.33 80.58,49.61 80.78,49.82 80.78,49.97 83.5,52.69 83.9,52.69 85.08,53.87 85.08,57.98 86.6,59.49 v1(88.27,59.49)
HOST_WAKE_BT_H: length 4.5
  TOP w0.127: R1174.1 127.07,22.87 126.1,22.87 R237.2 U18.6
HOST_WAKE_BT_H_GPIO0_A7_D: length 151.8
  TOP w0.127: R1173.2 74.2,81.57 74.13,81.5 74.13,74.33 v1(74.21,74.25) ; v1(124.65,25.14) 125.83,23.96 125.91,23.96 R237.1 ; v1(83.27,60.82) 83.27,63.2 82.2,64.27 82.2,67.44 80.52,69.13 v1(80.28,69.13) ; v1(79.89,57.47) 78.43,56.02 78.43,50.73 75.77,48.06 75.77,44.21 76.29,43.69 76.29,43.27 75.72,42.7 v1(75.72,41.94) ; M1.168 76.87,18.11 76.21,18.78 75.68,18.78 75.43,19.03 72.86,19.03 71.31,20.58 70.16,20.58 69.5,21.24 69.5,22.81 69.93,23.24 69.93,23.99 70.52,24.58 70.52,24.92 70.26,25.18 70.26,25.94 70.76,26.44 70.76,29.76 v1(70.52,30) 70.52,30.65 68.93,32.23 68.93,33.94 69.47,34.47 69.47,38.38 69.97,38.88 v1(69.97,42.2)
  BOTTOM w0.127: v1(79.89,57.47) 79.98,57.56 81.59,57.56 82.88,58.85 82.88,60.43 v1(83.27,60.82) ; v1(74.21,74.25) 74.21,73.81 76.03,71.99 77.54,71.99 80.28,69.25 v1(80.28,69.13) ; v1(70.52,30) 71.03,30.51 79.02,30.51 84.1,25.43 84.88,25.43 86.98,23.33 87.72,23.33 92.43,18.62 102.81,18.62 103.18,18.25 110.18,18.25 110.34,18.4 116.07,18.4 122.8,25.14 v1(124.65,25.14) ; v1(69.97,42.2) 75.47,42.2 v1(75.72,41.94)
HP_DET_L_GPIO0_B3_D: length 178.4
  TOP w0.127: v1(74.71,11.21) 74.71,4.99 73.44,3.72 68.94,3.72 68.28,3.06 v1(68.28,2.01) ; v1(64.91,19.53) 64.89,19.55 62.93,19.55 62.66,19.28 62.66,18.94 62.29,18.57 62.21,18.57 61.87,18.23 M1.153 ; v1(130.08,34.96) 130.08,38.51 131.86,40.29 131.86,42.83 130.46,44.23 130.46,46.51 130.59,46.64 133.26,46.64 v1(133.51,46.9) ; v1(132.44,70.49) 132.16,70.77 124.56,70.77 R455.1
  BOTTOM w0.127: v1(130.08,34.96) 128.81,33.69 128.81,24.04 127.03,22.26 123.6,22.26 122.08,20.73 122.08,17.18 124.24,15.02 124.24,12.48 125.74,10.98 125.74,8.8 122.73,5.79 122.52,5.79 120.28,5.79 120.07,6 118.76,6 118.27,5.52 99.55,5.52 98.18,4.15 96.35,4.15 95.5,4.99 87.19,4.99 86.75,4.56 86.75,2.2 86,1.45 77.13,1.45 76.9,1.22 69.08,1.22 v1(68.28,2.01) ; v1(74.71,11.21) 74.33,11.59 74.33,13.88 71.53,16.67 68.84,16.67 65.98,19.53 v1(64.91,19.53) ; v1(133.51,46.9) 133.51,47.78 133.76,48.04 133.76,69.17 v1(132.44,70.49)
HP_SNS: length 131.9
  TOP w0.254: J37.4 119.51,82.39 119.51,76.44 118.84,75.76 R316.2 118.84,71.88 120.84,69.88 131.77,69.88 133.35,68.3 133.35,48.13 132.75,47.53 130.33,47.53 129.73,46.92 129.73,45.65 128.43,44.36 v1(127.29,44.36) ; R306.1 91.45,25 v1(91.45,29.76) 91.45,30.66 88.81,33.31 86.37,33.31 83.29,30.23 83.29,29.65 82.83,29.19 M1.11
  BOTTOM w0.254: v1(127.29,44.36) 126.52,44.36 125.51,43.34 125.51,41.95 124.28,40.72 124.28,40.39 120.18,36.29 107.89,36.29 106.08,34.48 106.08,33.02 103.18,30.13 103.18,26.14 102.58,25.53 95.71,25.53 95.05,26.19 94.4,26.19 91.45,29.14 v1(91.45,29.76)
HPL_OUT: length 114.5
  TOP w0.254: C222.2 121.72,70.31 131.88,70.31 133.73,68.46 133.73,47.88 132.87,47.02 130.46,47.02 130.11,46.67 130.11,45.39 128.44,43.72 v1(126.78,43.72) ; C215.1 90.86,24.19 v1(90.86,30.5) 90.86,30.61 88.68,32.8 86.57,32.8 83.75,29.98 83.75,29.18 82.76,28.19 M1.10
  BOTTOM w0.254: v1(90.86,30.5) 90.86,29.19 94.24,25.81 94.89,25.81 95.55,25.15 102.74,25.15 103.56,25.98 103.56,29.97 106.46,32.86 106.46,34.32 107.22,35.08 112.25,35.08 113.07,35.91 120.34,35.91 124.66,40.23 124.66,40.56 126.02,41.92 126.02,42.96 v1(126.78,43.72)
HPL_OUT+: length 10.7
  TOP w0.254: J37.2 124.06,80.78 122.64,79.36 122.64,78.11 120.96,76.44 D66.1 120.96,73.92 120.99,73.89 R447.2 120.99,73 121.44,72.55 C222.1
HPR_OUT: length 113.7
  TOP w0.254: M1.12 82.59,30.19 86.22,33.81 88.86,33.81 v1(91.98,30.69) 91.98,30.16 91.98,30.16 91.98,25.56 92.24,25.31 C219.1 ; v1(127.79,44.99) 128.43,44.99 129.34,45.91 129.34,47.18 130.21,48.04 132.62,48.04 132.97,48.38 132.97,68.14 131.66,69.45 120.63,69.45 118.49,71.6 C224.2
  BOTTOM w0.254: v1(127.79,44.99) 126.4,44.99 125,43.59 125,41.98 123.89,40.88 123.89,40.55 120.02,36.67 107.73,36.67 105.7,34.64 105.7,33.18 102.8,30.29 102.8,26.3 102.42,25.91 95.86,25.91 95.21,26.57 94.56,26.57 91.98,29.15 91.98,30.64 91.98,30.64 v1(91.98,30.69)
HPR_OUT+: length 13.4
  TOP w0.254: J37.3 117.44,83.49 118.96,81.97 118.96,78.09 116.65,75.78 D68.1 117.13,73.97 C224.1
HUB_1V8: length 14.5
  TOP w0.254: C303.2 118.42,44.86 118.19,45.1 U7.9 ; C310.2 106.97,45.12 107.49,44.6 U7.29 ; C355.2 118.78,41.56 118.24,42.1 U7.3 ; C305.2 107.47,47.6 107.47,46.52 107.89,46.1 U7.26
  TOP w0.508: v1(118.65,45.55) 119.34,44.86 ; v1(119.13,40.77) 119.47,41.12 C355.2 ; C310.2 106.53,44.72 v1(106.79,44.46) ; v1(107.53,48.55) C305.2
HUB_3V3: length 21.8
  TOP w0.254: U7.32 107.72,43.1 107.17,42.55 C306.2 ; C309.1 112.69,50 U7.19 ; C308.1 107.09,46.58 107.09,46.26 107.76,45.6 U7.27
  TOP w0.508: v1(120.94,43.21) 120.63,43.21 R435.1 R436.1 ; R45.2 R48.1 103.34,39.9 104.33,38.91 105.63,38.91 ; R434.1 v1(120.42,39.28) ; C309.1 112.99,50 v1(113.37,50.38) ; C308.1 v1(106.53,47.78) ; v1(116.62,38.79) 116.62,37.02 116.27,36.67 R439.2 ; v1(107.73,38.62) 105.93,38.62 105.63,38.91 ; v1(106.53,43.14) C306.2 ; 105.63,38.91 R438.2
  vias: v1(111.08,38.34) v1(111.95,38.26) v1(116.01,49.23) v1(116.7,49.21)
HUB_DM1: length 11.3
  TOP w0.114: R49.1 103.72,53.62 103.72,51.92 105.91,49.73 110.1,49.73 110.56,49.28 110.56,49.02 110.69,48.89 U7.23
HUB_DM2: length 40.8
  TOP w0.114: R37.1 87.34,70.07 87.21,69.94 87.21,69.67 v1(87.49,69.39) ; v1(106.63,51.45) 106.91,51.17 107.89,51.17 108.36,50.69 110.92,50.69 112.06,49.55 112.06,49.23 112.19,49.1 U7.20
  BOTTOM w0.114: v1(87.49,69.39) 87.21,69.11 87.21,68.99 87.3,68.91 89.66,68.91 95.38,63.18 95.38,60.39 95.79,59.98 95.79,54.85 99.47,51.17 106.35,51.17 v1(106.63,51.45)
HUB_DM2_2: length 8.2
  TOP w0.114: J42.11 87.26,77.1 87.15,76.98 87.15,76.77 86.25,75.87 86.25,74.94 87.21,73.98 87.21,72.65 D8.2 87.21,71.69 87.21,71.29 R37.2
HUB_DM3: length 28.6
  TOP w0.114: R29.1 126.46,65.28 126.38,65.36 125.9,65.36 125.37,64.83 125.37,64.49 123.64,62.75 123.64,59.68 124.37,58.95 124.37,58.24 125.05,57.55 125.05,54.18 122.55,51.68 115.84,51.68 113.43,49.27 113.43,49.05 113.69,48.79 U7.17
HUB_DM3_2: length 6.5
  TOP w0.114: J7.2 132.11,64.19 132,64.3 130.96,64.3 130.01,65.25 129.04,65.25 D4.2 128.08,65.25 127.68,65.25 R29.2
HUB_DM4: length 16
  TOP w0.114: U7.14 115.19,48.89 114.93,49.15 114.93,49.66 116.21,50.94 122.85,50.94 125.79,53.88 125.79,54.53 125.95,54.69 126.38,54.69 126.46,54.61 R32.1
HUB_DM4_2: length 6.8
  TOP w0.114: R32.2 127.68,54.59 128.08,54.59 D6.2 129.04,54.59 129.41,54.59 131.12,52.87 132,52.87 132.11,52.76 J8.2
HUB_DP1: length 11.3
  TOP w0.114: R50.1 103.48,53.62 103.48,51.82 105.81,49.49 110,49.49 110.31,49.18 110.31,48.97 110.19,48.84 U7.24
HUB_DP2: length 40.8
  TOP w0.114: v1(86.69,69.39) 86.97,69.67 86.97,69.94 86.84,70.07 R38.1 ; v1(106.63,50.65) 106.91,50.93 107.79,50.93 108.26,50.45 110.82,50.45 111.82,49.45 111.82,49.23 111.69,49.1 U7.21
  BOTTOM w0.114: v1(86.69,69.39) 86.97,69.11 86.97,68.89 87.2,68.66 89.56,68.66 95.14,63.08 95.14,60.29 95.55,59.88 95.55,54.75 99.37,50.93 106.35,50.93 v1(106.63,50.65)
HUB_DP2_2: length 8.2
  TOP w0.114: J42.12 86.79,77.1 86.91,76.98 86.91,76.87 86.01,75.97 86.01,74.84 86.97,73.88 86.97,72.65 D9.1 86.97,71.69 86.97,71.29 R38.2
HUB_DP3: length 28.6
  TOP w0.114: U7.18 113.18,49.37 115.74,51.92 122.45,51.92 124.81,54.28 124.81,57.45 124.13,58.14 124.13,58.85 123.4,59.58 123.4,62.85 125.13,64.59 125.13,64.93 125.8,65.6 126.24,65.6 R30.1
HUB_DP3_2: length 6.5
  TOP w0.114: J7.3 132.11,64.66 132,64.54 131.06,64.54 130.11,65.5 129.04,65.5 D5.1 128.08,65.5 127.68,65.5 R30.2
HUB_DP4: length 16
  TOP w0.114: U7.15 114.69,49.76 116.11,51.18 122.75,51.18 125.55,53.98 125.55,54.63 125.85,54.93 126.24,54.93 R33.1
HUB_DP4_2: length 6.8
  TOP w0.114: J8.3 132.11,53.23 132,53.11 131.22,53.11 129.51,54.83 129.04,54.83 D7.1 128.08,54.83 127.68,54.83 R33.2
HUB_REXT: length 2.6
  TOP w0.127: R47.1 107.56,45.1 U7.28
HUB_VBUSM: length 2.6
  TOP w0.254: R437.1 107.61,41.6 U7.35
HUB_XIN: length 5.9
  TOP w0.203: XT1.3 120.56,49.24 C54.1 119.81,48.49 R43.2 118.52,48.49 118.27,48.24 118.27,46.77 118.1,46.6 U7.12
HUB_XOUT: length 7.6
  TOP w0.203: U7.11 118.13,46.1 118.63,46.59 118.63,47.31 R43.1 119.36,47.59 119.47,47.47 C53.2 120.12,47.47 120.68,48.04 121.78,48.04 XT1.1
HUB_XRSTJ: length 6.1
  TOP w0.127: U7.34 107.09,42.1 C311.2 106.02,42.04 104.75,42.04 R36.2 R45.1
I2C1_SCL_M1: length 52.3
  TOP w0.127: v1(23.3,16.58) 23.36,16.52 23.36,11.61 R15.2 R128.1 ; v1(32.5,29.49) 32.72,29.7 32.72,30.17 34.96,32.41 34.96,34.3 36.84,36.19 37.57,36.19
  BOTTOM w0.127: v1(32.5,29.49) 34.3,29.49 34.59,29.2 36.24,29.2 37.5,27.94 37.5,26.02 42.42,21.1 42.42,19.81 40.21,17.6 27.27,17.6 27.14,17.47 25.82,17.47 25.16,16.81 23.52,16.81 v1(23.3,16.58)
I2C1_SDA_M1: length 52.1
  TOP w0.127: v1(32.76,28.86) 32.97,29.08 32.97,29.99 35.21,32.23 35.21,34.2 36.2,35.19 37.57,35.19 ; v1(22.56,16.75) 22.41,16.6 22.41,15.87 22.56,15.71 22.56,12.65 22.41,12.5 22.41,11.67 R16.2 R129.1
  BOTTOM w0.127: v1(32.76,28.86) 34.2,28.86 34.28,28.95 36.13,28.95 37.24,27.84 37.24,25.92 42.17,20.99 42.17,19.92 40.1,17.85 27.16,17.85 27.03,17.72 25.72,17.72 25.05,17.06 22.87,17.06 v1(22.56,16.75)
I2C2_SCL_M1: length 91.5
  TOP w0.127: v1(61.16,20.05) 60.78,20.43 60.78,23.59 63.08,25.89 63.08,27.41 63.48,27.82 63.48,38.82 62.94,39.36 62.94,40.25 62.15,41.04 62.15,44.92 60.51,46.56 60.51,48.11 59.15,49.47 58.86,49.47 57.67,50.67 57.67,51.37 57.34,51.69 50.94,51.69 50.29,51.04 44.97,51.04 43.19,52.82 41.32,52.82 38.96,55.19 37.57,55.19 ; R126.1 40.36,10.45 39.84,10.45 R13.2 39.78,11.52 39.78,13.69 38.01,15.47 v1(38.01,16.2)
  BOTTOM w0.127: v1(38.01,16.2) 38.01,16.05 38.47,15.59 39.51,15.59 39.99,16.07 40.84,16.07 42.83,18.06 57.27,18.06 59.67,20.46 60.74,20.46 v1(61.16,20.05)
I2C2_SDA_M1: length 91.6
  TOP w0.127: 37.57,54.19 39.6,54.19 41.22,52.57 43.08,52.57 44.86,50.79 50.24,50.79 50.54,50.49 53.16,50.49 54.11,51.44 57.21,51.44 57.41,51.24 57.41,50.56 58.76,49.22 59.04,49.22 60.26,48.01 60.26,46.46 61.9,44.81 61.9,40.91 62.69,40.12 62.69,39.21 63.23,38.67 63.23,27.95 62.82,27.54 62.82,26 60.48,23.66 v1(60.48,19.99) ; v1(36.28,16.2) 36.28,15.78 37.79,14.27 37.79,11.48 R14.2 38.86,10.41 39.38,10.41 R127.1
  BOTTOM w0.127: v1(36.28,16.2) 37.34,16.2 38.21,15.33 39.61,15.33 40.1,15.82 40.95,15.82 42.94,17.81 57.68,17.81 59.86,19.99 v1(60.48,19.99)
I2C3_SCL_M0: length 135.9
  TOP w0.127: U59.9 15,32.29 16.16,31.13 v1(16.16,30.13) ; M1.71 53.87,61.89 54.42,61.34 57.98,61.34 60.74,58.58 62.14,58.58 62.97,57.74 62.97,55.7 63.14,55.53 65.46,53.21 65.46,52.16 69.25,48.38 69.25,48.17 69.25,38.92 68.96,38.64 68.96,34.68 68.43,34.15 68.43,31.54 69.53,30.44 69.53,28.76 68.53,27.76 68.53,27.08 67.09,25.64 67.09,23.86 67.09,19.59 v1(66.83,19.34) ; R343.1 69.56,10.7 R12.2 71.54,11.51 72.35,11.51 73.69,12.86 v1(74.84,12.86)
  BOTTOM w0.127: v1(16.16,30.13) 16.16,29.62 16.53,29.25 17.19,29.25 18.41,30.47 23.72,30.47 24.99,29.2 29.08,29.2 31.63,31.75 36.21,31.75 40.47,27.49 40.47,25.57 43.36,22.67 63.2,22.67 66.2,19.67 66.51,19.67 v1(66.83,19.34) 69.25,16.92 71.66,16.92 74.84,13.75 v1(74.84,12.86)
I2C3_SDA_M0: length 136.3
  TOP w0.127: v1(16.88,29.72) 16.88,30.81 15,32.69 U59.10 ; R344.1 69.27,10.4 69.68,10.4 69.98,10.7 R11.2 71.52,11.26 72.5,11.26 73.59,12.35 74.45,12.35 v1(74.84,11.97) ; M1.70 54.87,62.04 55.31,61.6 58.1,61.6 60.87,58.83 62.26,58.83 63.23,57.87 63.23,55.8 65.72,53.31 65.72,52.27 69.5,48.48 69.5,48.06 69.5,38.82 69.22,38.53 69.22,34.58 68.68,34.04 68.68,31.72 69.78,30.61 69.78,28.63 68.79,27.64 68.79,26.99 67.34,25.54 67.34,23.75 67.34,23.75 67.34,19.59 v1(67.6,19.34)
  BOTTOM w0.127: v1(74.84,11.97) 75.34,12.48 75.34,13.62 71.79,17.18 69.76,17.18 v1(67.6,19.34) 67.01,19.92 66.31,19.92 63.3,22.93 43.47,22.93 40.72,25.67 40.72,27.59 36.31,32 31.52,32 28.97,29.45 25.1,29.45 23.82,30.72 17.89,30.72 v1(16.88,29.72)
I2C5_SCL_M0/UART9_TX_M1: length 5.5
  TOP w0.127: J44.15 105.12,4.48 106.42,5.78 107.32,5.78 R425.2 108.24,7.08 R365.6
I2C5_SDA_M0/UART9_RX_M1: length 6.9
  TOP w0.127: J44.17 103.79,5.75 105.26,5.75 106.15,6.64 R426.2 106.66,7.4 107.48,7.4 107.69,7.61 R365.5
ILMT: length 2
  TOP w0.254: U70.10 23.25,55.31 23.02,55.53 R785.2
ISOLATEB: length 3.8
  BOTTOM w0.127: R156.2 75.98,54.49 75.8,54.67 75.09,54.67 73.89,55.87 U15.20
LAN0_A+: length 19.1
  BOTTOM w0.102: R169.2 51.24,64.01 51.24,64.1 51.65,64.5 51.65,64.87 D36.6 51.65,65.34 51.65,66.33 50.91,67.06 50.91,69.96 50.66,70.2 48.62,70.2 48.47,70.05 46.65,70.05 45.3,71.4 45.3,72.66 46.1,73.46 47.3,73.46 47.65,73.29 48,73.41 48.18,73.77 48.03,74.23 J22.2
LAN0_A-: length 19.1
  BOTTOM w0.102: J22.3 47.06,71.83 47.54,71.99 47.82,72.56 47.68,72.99 47.24,73.21 46.21,73.21 45.55,72.55 45.55,71.51 46.75,70.31 48.36,70.31 48.51,70.46 50.77,70.46 51.16,70.06 51.16,68.05 D36.1 51.16,67.56 51.16,67.17 51.9,66.43 51.9,64.4 51.49,63.99 51.49,63.83 R168.2
LAN0_B+: length 25.1
  TOP w0.102: v1(51.11,72.6) 51.38,72.88 51.38,73.55 50.64,74.29 49.75,74.29 48.47,75.57 44.84,75.57 44.23,74.96 44.23,73.31 44.61,72.93 45.37,72.93 45.88,73.44 45.88,74.2 45.5,74.58 J22.4
  BOTTOM w0.102: R167.2 53.18,63.92 53.18,64.04 52.84,64.38 52.84,65.82 53.53,66.51 53.53,67.58 D36.3 53.53,68.03 53.53,69.4 51.38,71.54 51.38,72.33 v1(51.11,72.6)
LAN0_B-: length 25.2
  TOP w0.102: v1(51.91,72.6) 51.64,72.88 51.64,73.65 50.74,74.54 49.86,74.54 48.57,75.83 44.74,75.83 43.97,75.06 43.97,73.85 42.17,72.04 J22.7
  BOTTOM w0.102: R166.2 53.44,63.92 53.44,64.15 53.09,64.49 53.09,64.89 D36.4 53.09,65.32 53.09,65.71 53.78,66.4 53.78,69.5 51.64,71.65 51.64,72.33 v1(51.91,72.6)
LAN0_C+: length 25.2
  BOTTOM w0.102: J22.5 43.81,72.14 43.37,73.03 43.37,73.21 43.52,73.36 44.18,73.69 44.18,75.09 44.74,75.65 48.55,75.65 49.87,74.33 51.71,74.33 52.54,73.5 52.54,71.43 54.97,69 54.97,66.86 55.46,66.37 55.46,65.97 55.71,65.71 55.71,65.34 D35.6 55.71,64.87 55.71,64.6 55.59,64.49 55.41,64.49 55.09,64.17 55.09,63.92 R165.2
LAN0_C-: length 25.2
  BOTTOM w0.102: J22.6 43.29,73.66 43.45,73.61 43.92,73.85 43.92,75.19 44.64,75.9 48.65,75.9 49.97,74.58 51.82,74.58 52.8,73.6 52.8,71.53 55.23,69.1 55.23,68.05 D35.1 55.23,67.56 55.23,66.96 55.71,66.48 55.71,66.07 55.96,65.82 55.96,64.5 55.7,64.23 55.51,64.23 55.34,64.06 55.34,63.92 R164.2
LAN0_D+: length 33.1
  BOTTOM w0.102: J22.8 40.55,73.82 40.28,73.29 39.78,73.12 39.52,73.25 39.17,74.29 39.17,74.96 40.6,76.39 48.95,76.39 50.2,75.14 51.94,75.14 53.28,73.8 53.28,71.73 55.71,69.3 56.77,69.3 57.61,68.46 57.61,68.05 D35.3 57.61,67.56 57.61,66.63 56.89,65.91 56.89,64.48 57.31,64.06 57.31,63.88 57.29,63.86 57.29,63.84 R163.2
LAN0_D-: length 33.1
  BOTTOM w0.102: R162.2 57.56,63.98 57.56,64.17 57.15,64.58 57.15,64.88 D35.4 57.15,65.33 57.15,65.81 57.87,66.53 57.87,68.56 56.87,69.56 55.81,69.56 53.53,71.84 53.53,73.91 52.05,75.39 50.3,75.39 49.06,76.64 40.5,76.64 38.92,75.06 38.92,74.25 39.31,73.07 39.4,72.8 J22.9
